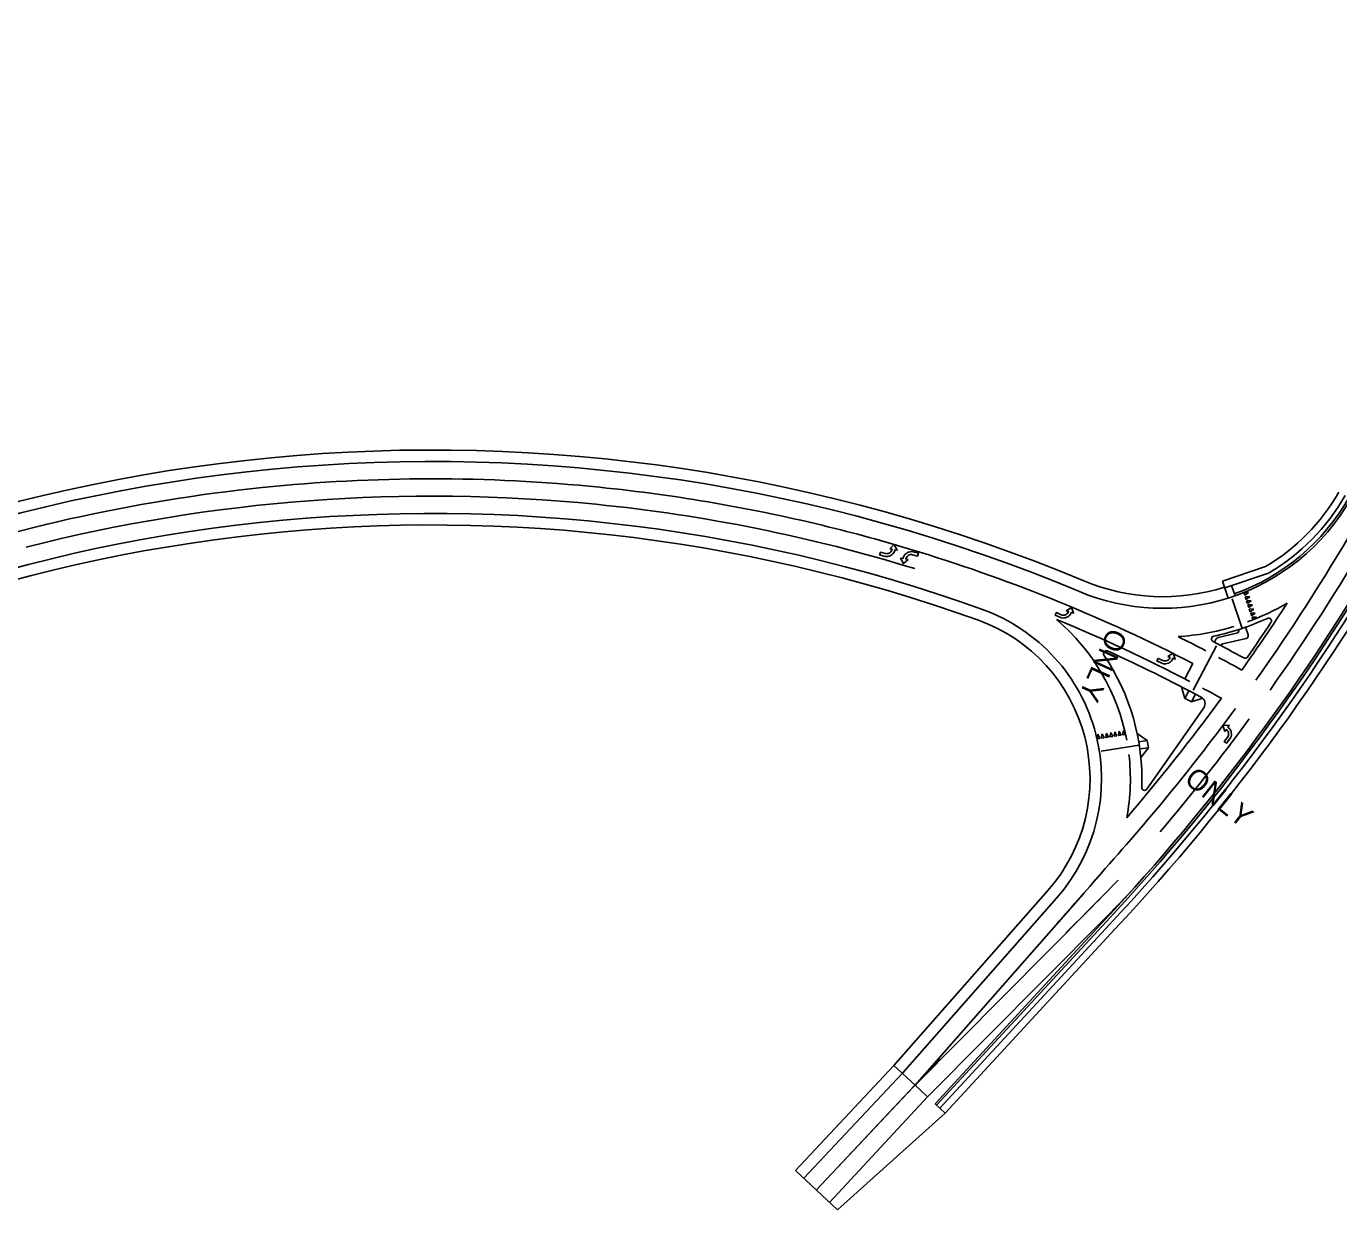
# Model space of a CAD drawing. Extents: x 979036 to 996074, y 1836928 to 1845163.
# Drawn here: x 991466 to 992377, y 1839134 to 1839955 of the extents above; entities that cross this region are included whole.
import ezdxf

# ---------------------------------------------------------------- set-up
doc = ezdxf.new("R2010")
doc.units = 0
for name, color, linetype in [('R_Proposed Road', 7, 'Continuous'), ('STRIPE_White Crosswalk', 7, 'Continuous'), ('STRIPE_White Stopbar', 7, 'Continuous'), ('STRIPE_White Turn Arrow', 7, 'Continuous'), ('STRIPE_White_6in', 7, 'Continuous'), ('STRIPE_White_ONLY', 7, 'Continuous'), ('STRIPE_White_Yield Tri', 7, 'Continuous'), ('STRIPE_Yellow Dbl 6in', 7, 'Continuous'), ('STRIPE_Yellow_10_30 SKIP', 7, 'Continuous')]:
    doc.layers.add(name, color=color, linetype=linetype)

msp = doc.modelspace()

# ---------------------------------------------------------------- linework, layer by layer
at = {"layer": 'R_Proposed Road'}
for p, q in [((992296, 1839569.74), (992325.84, 1839579.77)), ((992297.59, 1839565), (992327.92, 1839575.2)), ((992296, 1839569.74), (992299.98, 1839557.89)), ((992302.33, 1839566.59), (992304.72, 1839559.48)), ((992312.05, 1839537.68), (992313.83, 1839532.37)), ((992291.68, 1839529.62), (992290.44, 1839527.27)), ((992293.02, 1839530.64), (992305.85, 1839533.46)), ((992295.04, 1839525.26), (992294.87, 1839524.94)), ((992295.02, 1839525.23), (992294.87, 1839524.94)), ((992296.36, 1839526.26), (992312.37, 1839529.78)), ((992267.47, 1839496.38), (992269.97, 1839488.32)), ((992269.97, 1839488.32), (992272.77, 1839493.63)), ((992274.4, 1839485.99), (992277.19, 1839491.3)), ((992243.6, 1839425.3), (992283.02, 1839481.87)), ((992282.28, 1839488.43), (992274.4, 1839485.99)), ((992236.77, 1839464.04), (992243.83, 1839459.05)), ((992237.89, 1839458.14), (992243.83, 1839459.05)), ((992238.65, 1839453.2), (992244.59, 1839454.11)), ((992244.59, 1839454.11), (992239.35, 1839447.23)), ((992174.88, 1839355.07), (992067.98, 1839233.7)), ((992096.46, 1839207.05), (992214.39, 1839334.58)), ((992097.56, 1839206.03), (992215.49, 1839333.56)), ((992099.75, 1839203.98), (992217.68, 1839331.51)), ((992103.4, 1839200.56), (992221.33, 1839328.09)), ((992067.98, 1839233.69), (991999.62, 1839160.71)), ((992067.98, 1839233.7), (992082.59, 1839220.03)), ((992073.83, 1839228.23), (992005.28, 1839155.42)), ((992091.35, 1839211.83), (992082.59, 1839220.03)), ((992091.35, 1839211.83), (992023.29, 1839138.57)), ((992103.4, 1839200.56), (992096.46, 1839207.05)), ((992103.4, 1839200.56), (992028.7, 1839133.51)), ((991999.62, 1839160.71), (992028.7, 1839133.51))]:
    msp.add_line(p, q, dxfattribs=at)
for centre, radius, start, end in [((991155.19, 1840325.41), 1451.89, 316.91039, 344.93538), ((991155.19, 1840325.41), 1454.89, 316.91039, 344.93538), ((991155.19, 1840325.41), 1459.89, 316.91039, 344.93538), ((991747.45, 1838488.74), 1171.92, 67.29702, 123.64915), ((992254.56, 1839700.85), 150, 287.62458, 330.39897), ((992254.56, 1839700.85), 148.5, 289.54418, 330.39897), ((992254.56, 1839700.85), 140.5, 300.48439, 330.39897), ((992254.56, 1839700.85), 145.5, 300.27732, 330.39897), ((991747.45, 1838488.74), 1119.92, 70.20618, 123.64915), ((991155.19, 1840325.41), 1450.39, 316.91039, 329.86783), ((992254.56, 1839700.85), 142, 247.29702, 287.57078), ((992254.56, 1839700.85), 173, 281.8124, 294.81368), ((992328, 1839542.01), 2, 326.25843, 114.81368), ((992087.07, 1839432.4), 117, 318.6287, 70.20618), ((992305.42, 1839535.42), 2, 282.41253, 18.57956), ((991155.19, 1840325.41), 1412.39, 325.08485, 326.25843), ((992290.39, 1839529.56), 2, 101.8124, 242.45151), ((991747.45, 1838488.74), 1171.92, 61.27106, 62.45151), ((992293.45, 1839528.69), 2, 102.72771, 152.27507), ((992296.79, 1839524.3), 2, 102.41253, 152.27507), ((992311.94, 1839531.73), 2, 282.41253, 18.57956), ((992215.34, 1839519.42), 2, 65.584, 214.15659), ((992087.07, 1839432.4), 153, 357.79675, 34.15659), ((991747.45, 1838488.74), 1133.92, 61.91516, 65.584), ((992311.71, 1839518.15), 2, 241.27106, 325.08485), ((992278.92, 1839484.73), 5, 325.12923, 61.91516), ((991747.45, 1838488.74), 1127.92, 62.14808, 62.40207), ((992087.07, 1839432.4), 159, 7.84245, 9.64996), ((992241.96, 1839426.44), 2, 177.79675, 325.0505)]:
    msp.add_arc(centre, radius, start, end, dxfattribs=at)
at = {"layer": 'STRIPE_White Crosswalk'}
for p, q in [((992302.79, 1839557.37), (992309.68, 1839536.87)), ((992291.97, 1839524.79), (992275.75, 1839493.94)), ((992211.85, 1839451.6), (992238.28, 1839455.74))]:
    msp.add_line(p, q, dxfattribs=at)
at = {"layer": 'STRIPE_White Stopbar'}
for p, q in [((992269.83, 1839501.92), (992275.33, 1839512.58)), ((992275.33, 1839512.58), (992269.83, 1839501.91))]:
    msp.add_line(p, q, dxfattribs=at)
at = {"layer": 'STRIPE_White Turn Arrow'}
for points in [[(992065.02, 1839592.05), (992068.18, 1839595.06), (992070.29, 1839591.24), (992068.64, 1839591.49), (992068.48, 1839590.84), (992068.3, 1839590.29), (992067.94, 1839589.56), (992067.36, 1839588.74), (992066.77, 1839588.13), (992066.09, 1839587.69), (992065.31, 1839587.17), (992064.55, 1839586.96), (992063.72, 1839586.73), (992062.74, 1839586.7), (992061.75, 1839586.79), (992057.99, 1839587.82), (992058.51, 1839589.75), (992061.99, 1839588.84), (992062.67, 1839588.72), (992063.43, 1839588.75), (992064.28, 1839588.92), (992065.04, 1839589.32), (992065.33, 1839589.55), (992065.84, 1839590.06), (992066.27, 1839590.74), (992066.56, 1839591.42), (992066.67, 1839591.8)], [(992077.83, 1839584.79), (992074.66, 1839581.8), (992072.57, 1839585.63), (992074.22, 1839585.37), (992074.38, 1839586.01), (992074.56, 1839586.56), (992074.93, 1839587.3), (992075.52, 1839588.11), (992076.1, 1839588.72), (992076.78, 1839589.16), (992077.57, 1839589.67), (992078.33, 1839589.88), (992079.16, 1839590.11), (992080.14, 1839590.13), (992081.13, 1839590.03), (992084.89, 1839588.98), (992084.36, 1839587.05), (992080.89, 1839587.98), (992080.21, 1839588.11), (992079.44, 1839588.08), (992078.59, 1839587.92), (992077.83, 1839587.52), (992077.54, 1839587.29), (992077.02, 1839586.79), (992076.59, 1839586.11), (992076.3, 1839585.43), (992076.19, 1839585.05)], [(992187.57, 1839549.04), (992191.19, 1839551.48), (992192.62, 1839547.36), (992191.04, 1839547.89), (992190.78, 1839547.28), (992190.51, 1839546.76), (992190.03, 1839546.1), (992189.32, 1839545.39), (992188.64, 1839544.88), (992187.9, 1839544.56), (992187.04, 1839544.18), (992186.26, 1839544.1), (992185.4, 1839544.01), (992184.43, 1839544.14), (992183.47, 1839544.4), (992179.93, 1839546.04), (992180.77, 1839547.86), (992184.04, 1839546.38), (992184.69, 1839546.15), (992185.45, 1839546.05), (992186.32, 1839546.08), (992187.13, 1839546.34), (992187.46, 1839546.53), (992188.05, 1839546.94), (992188.58, 1839547.54), (992188.98, 1839548.16), (992189.15, 1839548.52)], [(992258.11, 1839517.28), (992261.73, 1839519.72), (992263.17, 1839515.6), (992261.58, 1839516.13), (992261.32, 1839515.51), (992261.05, 1839515), (992260.57, 1839514.34), (992259.86, 1839513.63), (992259.18, 1839513.12), (992258.44, 1839512.8), (992257.59, 1839512.42), (992256.8, 1839512.34), (992255.94, 1839512.25), (992254.97, 1839512.38), (992254.01, 1839512.64), (992250.47, 1839514.28), (992251.31, 1839516.1), (992254.58, 1839514.62), (992255.23, 1839514.39), (992255.99, 1839514.29), (992256.86, 1839514.32), (992257.68, 1839514.58), (992258, 1839514.77), (992258.59, 1839515.18), (992259.12, 1839515.78), (992259.52, 1839516.4), (992259.69, 1839516.76)], [(992297.73, 1839465.31), (992296.3, 1839469.43), (992300.64, 1839469.77), (992299.73, 1839468.38), (992300.26, 1839467.96), (992300.68, 1839467.57), (992301.2, 1839466.94), (992301.71, 1839466.07), (992302.02, 1839465.29), (992302.15, 1839464.49), (992302.29, 1839463.57), (992302.17, 1839462.78), (992302.05, 1839461.93), (992301.67, 1839461.03), (992301.17, 1839460.17), (992298.69, 1839457.16), (992297.14, 1839458.43), (992299.4, 1839461.22), (992299.8, 1839461.79), (992300.08, 1839462.5), (992300.28, 1839463.34), (992300.23, 1839464.2), (992300.13, 1839464.56), (992299.89, 1839465.24), (992299.44, 1839465.91), (992298.94, 1839466.45), (992298.64, 1839466.71)]]:
    msp.add_lwpolyline(points, close=True, dxfattribs=at)
at = {"layer": 'STRIPE_White_6in'}
for p, q in [((992180.88, 1839349.78), (992073.83, 1839228.23)), ((992213.82, 1839335.12), (992091.35, 1839211.83)), ((992073.83, 1839228.23), (992005.28, 1839155.42)), ((992091.35, 1839211.83), (992023.29, 1839138.57))]:
    msp.add_line(p, q, dxfattribs=at)
for centre, radius, start, end in [((991747.45, 1838488.74), 1163.92, 67.29702, 123.64915), ((991747.45, 1838488.74), 1127.92, 70.20618, 123.64915), ((992254.56, 1839700.85), 150, 247.29702, 287.62458), ((991155.19, 1840325.41), 1414.39, 324.69465, 326.97089), ((992254.56, 1839700.85), 170, 290.28061, 300.56441), ((992087.07, 1839432.4), 125, 318.6287, 70.20618), ((992087.07, 1839432.4), 145, 10.72183, 49.77151), ((991747.45, 1838488.74), 1139.92, 62.52605, 67.66076), ((992254.56, 1839700.85), 170, 273.57208, 286.8785), ((991747.45, 1838488.74), 1163.92, 62.52089, 63.58984), ((991747.45, 1838488.74), 1163.92, 61.128, 62.02926), ((991747.45, 1838488.74), 1139.92, 61.27449, 62.02409), ((991155.19, 1840325.41), 1414.39, 319.42853, 323.71513), ((991155.19, 1840325.41), 1438.39, 319.72797, 323.71128), ((992087.07, 1839432.4), 145, 349.30495, 6.70593), ((991184.26, 1840357.06), 1450.64, 315.21264, 316.26486)]:
    msp.add_arc(centre, radius, start, end, dxfattribs=at)
at = {"layer": 'STRIPE_White_Yield Tri'}
for p, q in [((992310.82, 1839561.73), (992311.46, 1839559.83)), ((992314, 1839561.67), (992310.82, 1839561.73)), ((992311.46, 1839559.83), (992314, 1839561.67)), ((992311.78, 1839558.88), (992312.41, 1839556.99)), ((992314.96, 1839558.83), (992311.78, 1839558.88)), ((992312.41, 1839556.99), (992314.96, 1839558.83)), ((992312.73, 1839556.04), (992313.37, 1839554.15)), ((992315.92, 1839555.99), (992312.73, 1839556.04)), ((992313.37, 1839554.15), (992315.92, 1839555.99)), ((992313.69, 1839553.2), (992314.33, 1839551.3)), ((992316.87, 1839553.14), (992313.69, 1839553.2)), ((992314.33, 1839551.3), (992316.87, 1839553.14)), ((992314.64, 1839550.35), (992315.28, 1839548.46)), ((992317.83, 1839550.3), (992314.64, 1839550.35)), ((992315.28, 1839548.46), (992317.83, 1839550.3)), ((992315.6, 1839547.51), (992316.24, 1839545.61)), ((992318.78, 1839547.46), (992315.6, 1839547.51)), ((992316.24, 1839545.61), (992318.78, 1839547.46)), ((992316.56, 1839544.67), (992317.19, 1839542.77)), ((992319.74, 1839544.61), (992316.56, 1839544.67)), ((992317.19, 1839542.77), (992319.74, 1839544.61)), ((992209.53, 1839463.38), (992208.93, 1839460.25)), ((992210.91, 1839460.56), (992209.53, 1839463.38)), ((992212.49, 1839463.83), (992211.9, 1839460.71)), ((992213.87, 1839461.01), (992212.49, 1839463.83)), ((992215.46, 1839464.29), (992214.86, 1839461.16)), ((992214.86, 1839461.16), (992216.84, 1839461.47)), ((992216.84, 1839461.47), (992215.46, 1839464.29)), ((992218.43, 1839464.75), (992217.83, 1839461.62)), ((992217.83, 1839461.62), (992219.8, 1839461.92)), ((992219.8, 1839461.92), (992218.43, 1839464.75)), ((992221.39, 1839465.2), (992220.79, 1839462.08)), ((992220.79, 1839462.08), (992222.77, 1839462.38)), ((992222.77, 1839462.38), (992221.39, 1839465.2)), ((992224.36, 1839465.66), (992223.76, 1839462.53)), ((992223.76, 1839462.53), (992225.73, 1839462.84)), ((992225.73, 1839462.84), (992224.36, 1839465.66)), ((992227.32, 1839466.12), (992226.72, 1839462.99)), ((992226.72, 1839462.99), (992228.7, 1839463.29)), ((992228.7, 1839463.29), (992227.32, 1839466.12)), ((992208.93, 1839460.25), (992210.91, 1839460.56)), ((992211.9, 1839460.71), (992213.87, 1839461.01))]:
    msp.add_line(p, q, dxfattribs=at)
at = {"layer": 'STRIPE_Yellow Dbl 6in'}
for p, q in [((992197.44, 1839350.44), (992082.59, 1839220.03)), ((992197.44, 1839350.44), (992082.59, 1839220.03)), ((992205.05, 1839343.32), (992082.59, 1839220.03)), ((992205.05, 1839343.32), (992082.59, 1839220.03)), ((992099.74, 1839238.25), (992014.01, 1839147.19)), ((992082.56, 1839220), (992014.01, 1839147.19))]:
    msp.add_line(p, q, dxfattribs=at)
for centre, radius, start, end in [((991747.99, 1838488.52), 1151.92, 67.84643, 72.93861), ((991747.45, 1838488.74), 1151.92, 62.72507, 67.81726), ((991155.19, 1840325.41), 1426.39, 317.96261, 323.71513), ((991126.12, 1840293.76), 1427.44, 317.63333, 319.68767), ((991126.12, 1840293.76), 1427.44, 318.63545, 319.68767), ((991126.12, 1840293.76), 1427.44, 318.63545, 319.68767), ((991184.26, 1840357.06), 1438.64, 314.20368, 316.25099), ((991184.26, 1840357.06), 1438.64, 315.19877, 316.25099), ((991184.26, 1840357.06), 1438.64, 315.19877, 316.25099)]:
    msp.add_arc(centre, radius, start, end, dxfattribs=at)
at = {"layer": 'STRIPE_Yellow_10_30 SKIP'}
for centre, radius, start, end in [((991155.19, 1840325.41), 1426.39, 324.69465, 344.93538), ((991155.19, 1840325.41), 1426.39, 324.69465, 344.93538), ((991155.19, 1840325.41), 1438.39, 324.69465, 344.93538), ((991155.19, 1840325.41), 1438.39, 324.69465, 344.93538), ((991747.45, 1838488.74), 1151.92, 95.87812, 109.3769), ((991747.45, 1838488.74), 1151.92, 95.87812, 109.3769), ((991747.45, 1838488.74), 1151.92, 84.20801, 95.87813), ((991747.45, 1838488.74), 1151.92, 84.20801, 95.87813), ((991747.45, 1838488.74), 1151.92, 76.15629, 84.20801), ((991747.45, 1838488.74), 1151.92, 76.15629, 84.20801), ((991747.45, 1838488.74), 1139.92, 84.27958, 104.31496), ((991747.45, 1838488.74), 1139.92, 84.27958, 104.31496), ((991747.45, 1838488.74), 1139.92, 72.9096, 84.278), ((991747.45, 1838488.74), 1139.92, 72.9096, 84.278), ((991747.45, 1838488.74), 1151.92, 72.91215, 76.15632), ((991747.45, 1838488.74), 1151.92, 72.91215, 76.15632)]:
    msp.add_arc(centre, radius, start, end, dxfattribs=at)

# ---------------------------------------------------------------- texts
at = {"layer": 'STRIPE_White_ONLY'}
for rotation, p in [(245.70413, (992217.51, 1839538.06)), (321.35141, (992268.7, 1839430.57))]:
    msp.add_text('ONLY', height=14.4, rotation=rotation, dxfattribs=at).set_placement(p)

doc.saveas('drawing.dxf')
